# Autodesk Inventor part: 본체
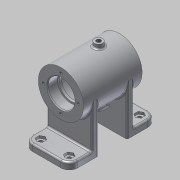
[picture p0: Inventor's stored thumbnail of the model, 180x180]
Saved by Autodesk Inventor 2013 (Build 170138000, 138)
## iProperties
Created: 2017-02
Part Number: 본체
Material: 알루미늄 6061
Document SubType Name: Modeling
Designer: Administrator
Mass: 355.288 g
Surface Area: 424.021 cm^2
Volume: 131.103 cm^3
Density: 2.71 g/cm^3
Author: Administrator
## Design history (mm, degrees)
sketch "스케치2"
  geometry: L1 (0, 16)-(0, 27); L2 (0, 27)-(70, 27); L3 (0, 16)-(12, 16); L4 (12, 16)-(12, 14); L5 (12, 14)-(15, 14); L6 (15, 14)-(15, 22); L7 (15, 22)-(55, 22); L8 (55, 22)-(55, 14); L9 (55, 14)-(58, 14); L10 (58, 14)-(58, 16); L11 (58, 16)-(70, 16); L12 (70, 16)-(70, 27); L13 (0, 0)-(70, 0)
  constraints: 26 end point, 7 perpendicular, 5 parallel, 1 point on line, 1 vertical
  dimensions: "d0" = 54 diameter of L2 L13; "d2" = 12 distance between parallel lines of L4 L1; "d3" = 12 distance between parallel lines of L12 L10; "d4" = 70 distance between parallel lines of L1 L12; "d5" = 40 distance between parallel lines of L8 L6; "d6" = 3 distance between parallel lines of L6 L4; "d7" = 32 diameter of L3 L13; "d8" = 44 diameter of L7 L13; "d9" = 28 diameter of L5 L13; "d10" = 28 diameter of L9 L13; "d11" = 32 diameter of L11 L13; "d12" = 70 distance of L13.start L13.end
revolve "회전1" sketch "스케치2" stored, may be unused: angle "d13" = 90 deg
node "작업 평면1"
sketch "스케치3"
  geometry: L1 (27, 70)-(-27, 70) reference; C1 r 5 at (0, 45); 1 further point
  constraints: 1 centre point, 1 vertical alignment
  dimensions: "d16" = 10 diameter of C1; "d121" = 25 distance from line of C1.centre L1
extrude "돌출1" join sketch "스케치3" stored distance "d17" = 10; taper "d18" = 0 deg
sketch "스케치4"
  geometry: C1 r 5 at (0, 0) reference; 1 further point
hole "구멍1" sketch "스케치4" at (0, 0) diameter "d19" = 5.242; stored, may be unused: countersink angle "d23" = 90 deg, drill point angle "d25" = 118 deg; dims "d20" = 6, "d21" = 4, "d22" = 2, "d24" = 8
node "작업 평면2"
sketch "스케치5"
  geometry: L1 (0, 0)-(16.339, -25.16); L2 (0, 0)-(0, -27)
  constraints: 4 end point, 1 vertical, 1 vertical alignment, 1 other
  dimensions: "d26" = 30 distance of L1.start L1.end; "d27" = 33 deg angle of L2 L1
node "작업 평면3"
sketch "스케치6"
  geometry: C1 r 6 at (0, 0); 1 further point
  constraints: 1 centre point
  dimensions: "d28" = 12 diameter of C1
extrude "돌출2" join sketch "스케치6" stored distance "d30" = 10; taper "d31" = 0 deg
sketch "스케치7"
  geometry: C1 r 6 at (0, 0) reference; C2 r 3 at (0, 0); 1 further point
  constraints: 1 centre point, 1 coincident
  dimensions: "d32" = 6 diameter of C2
hole "구멍2" sketch "스케치7" at (0, 0) diameter "d34" = 5.242; stored, may be unused: countersink angle "d38" = 90 deg, drill point angle "d40" = 118 deg; dims "d35" = 6, "d36" = 4, "d37" = 2, "d39" = 8
node "작업 평면4"
sketch "스케치8"
  geometry: L1 (27, 0)-(-27, 0) reference; L2 (27, 70)-(-27, 70) reference; L3 (0, 70)-(0, 0); L4 (0, 35)-(-27, 35); L5 (-27, 87)-(27, 87); L6 (27, -17)-(-27, -17); L7 (-27, 52)-(27, 52); L8 (-27, 87)-(-27, 52); L9 (27, 52)-(27, 87); L10 (27, 18)-(-27, 18); L11 (-27, -17)-(-27, 18); L12 (27, 18)-(27, -17); 2 further points
  constraints: 20 end point, 5 parallel, 5 perpendicular, 2 midpoint, 1 horizontal, 1 point on line, 2 other
  dimensions: "d48" = 104 distance between parallel lines of L6 L5; "d49" = 52 distance between parallel lines of L5 L4; "d50" = 27 distance between parallel lines of L3 L8; "d51" = 27 distance between parallel lines of L11 L3; "d52" = 54 distance between parallel lines of L9 L8; "d53" = 17 distance between parallel lines of L4 L7; "d54" = 27 distance of L4.start L4.end; "d55" = 17 distance between parallel lines of L10 L4
extrude "돌출3" join sketch "스케치8" distance "d56" = 8; taper "d57" = 0 deg
fillet "모깎기1" dims "d58" = 10
sketch "스케치9"
  geometry: L1 (27, -7)-(27, 18) reference; L2 (27, 18)-(-27, 18) reference; L3 (-17, 87)-(17, 87) reference; L4 (27, 77)-(27, 52) reference; L5 (27, 52)-(-27, 52) reference; L6 (-27, 52)-(-27, 77) reference; L7 (-27, 18)-(27, 18); L8 (27, 18)-(27, 10); L9 (27, 10)-(-27, 10); L10 (-27, 10)-(-27, 18); L11 (-27, 52)-(27, 52); L12 (27, 52)-(27, 60); L13 (27, 60)-(-27, 60); L14 (-27, 60)-(-27, 52); A1 r 10 centre (-17, 77) between (-17, 87) and (-27, 77) reference; A2 r 10 centre (17, 77) between (27, 77) and (17, 87) reference; 1 further point
  constraints: 16 end point, 4 parallel, 2 horizontal, 2 perpendicular, 2 point on line
  dimensions: "d59" = 8 distance between parallel lines of L11 L13; "d61" = 8 distance between parallel lines of L9 L2
extrude "돌출4" join sketch "스케치9" stored distance "d62" = 8; taper "d63" = 0 deg
sketch "스케치10" dims "d64" = 9
  geometry: L1 (-21.5, -4.402)-(-17, -1.804); L2 (-17, -1.804)-(-12.5, -4.402); L3 (-12.5, -4.402)-(-12.5, -9.598); L4 (-12.5, -9.598)-(-17, -12.196); L5 (-17, -12.196)-(-21.5, -9.598); L6 (-21.5, -9.598)-(-21.5, -4.402); A1 r 10 centre (-17, -7) between (-27, -7) and (-17, -17) reference; 4 further points
  constraints: 12 end point, 2 coincident, 2 horizontal alignment, 1 midpoint, 15 other
extrude "돌출5" cut sketch "스케치10" distance "d66" = 3; taper "d67" = 0 deg
sketch "스케치11"
  geometry: L1 (-21.5, -4.402)-(-17, -1.804) reference; L2 (-21.5, -9.598)-(-21.5, -4.402) reference; L3 (-17, -12.196)-(-21.5, -9.598) reference; L4 (-12.5, -9.598)-(-17, -12.196) reference; L5 (-12.5, -4.402)-(-12.5, -9.598) reference; L6 (-17, -1.804)-(-12.5, -4.402) reference; C1 r 2.5 at (-17, -7); A1 r 10 centre (-17, -7) between (-27, -7) and (-17, -17) reference; 1 further point
  constraints: 1 centre point, 1 coincident
  dimensions: "d68" = 5 diameter of C1
extrude "돌출6" cut sketch "스케치11" stored distance "d70" = 3; taper "d71" = 0 deg
fillet "모깎기2" dims "d72" = 2
fillet "모깎기3" dims "d79" = 2
fillet "모깎기4" dims "d80" = 2
fillet "모깎기5" dims "d81" = 2
fillet "모깎기6" dims "d82" = 0.3
fillet "모깎기7" dims "d83" = 2
sketch "스케치12" dims "d84" = 42
  geometry: C1 r 27 at (0, 0) reference; C2 r 16 at (0, 0) reference; C3 r 2.5 at (0, 21); 1 further point
  constraints: 2 vertical alignment, 1 centre point, 1 coincident, 2 other
  dimensions: "d86" = 5 diameter of C3
hole "구멍3" sketch "스케치12" at (0, 21) diameter "d87" = 3.242; stored, may be unused: countersink angle "d91" = 90 deg, drill point angle "d93" = 118 deg; dims "d88" = 8, "d89" = 4, "d90" = 2, "d92" = 10
sketch "스케치13"
  geometry: C1 r 1.621 at (0, -21) reference
hole "구멍4" sketch "스케치13" at (0, -21) diameter "d97" = 3.242; stored, may be unused: countersink angle "d101" = 90 deg, drill point angle "d103" = 118 deg; dims "d98" = 8, "d99" = 4, "d100" = 2, "d102" = 10
chamfer "모따기1" distance "d107" = 1; stored, may be unused: second distance "d108" = 2, angle "d109" = 45 deg
fillet "모깎기8" dims "d110" = 2
node "작업 평면5"
node "작업 평면6"
sketch "스케치15"
  geometry: L1 (-51.946, 2.402)-(-18.054, 2.402); L2 (-18.054, 2.402)-(-18.054, -2.402); L3 (-18.054, -2.402)-(-51.946, -2.402); L4 (-51.946, -2.402)-(-51.946, 2.402); L5 (-51.946, 0)-(-18.054, 0); L6 (-35, 2.402)-(-35, -2.402); L7 (0, 27)-(-70, 27) reference; L8 (-70, 27)-(-70, -27) reference; 1 further point
  constraints: 4 end point, 4 midpoint, 2 other
  dimensions: "d117" = 27 distance between parallel lines of L5 L7; "d118" = 35 distance between parallel lines of L8 L6
feature "엠보싱2" sketch "스케치15" dims "d17" = 10, "d18" = 0, "d119" = 0.5, "d120" = 0
node "솔리드1"
pattern_linear "직사각형 패턴1" dims "d75" = 34, "d78" = 84
pattern_circular "원형 패턴1" dims angle "d95" = 360 deg
pattern_circular "원형 패턴2" dims angle "d105" = 360 deg
node "투영된 루프1"
node "투영된 루프2"
node "투영된 루프3"
other parameters: "d14" = 32, "d111" = 58.5, "d116" = -96.75
